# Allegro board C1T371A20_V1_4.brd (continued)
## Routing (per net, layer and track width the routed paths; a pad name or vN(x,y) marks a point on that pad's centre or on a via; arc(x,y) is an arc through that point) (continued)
TL_MSPIIO3: length 12.1
  TOP w0.2: U2.3 39.6,42.48 37.9,40.78 36.6,40.78 35,39.18 35,36.28 34.6,35.88 33.72,35.88 33.4,36.2 U5.7
TL_MSPIMISO: length 11.6
  TOP w0.2: U5.2 36.58,36.2 35.9,36.88 35.9,38.98 36.9,39.98 38.2,39.98 40.3,42.08 U2.5
TL_MSPIMOSI: length 11.6
  TOP w0.2: U2.1 38.9,42.78 37.7,41.58 36.39,41.58 34.1,39.29 34.1,38.38 33.83,38.11 31.97,38.11 31.77,38.3 31.77,38.59 31.93,38.75 32.86,38.75 U5.5
TL_PA0: length 22.5
  TOP w0.2: U2.30 48.65,45.99 53.26,41.38 55.5,41.38 57.9,38.98 65.5,38.98 66.6,40.08 J7.19
TL_PA1: length 15.5
  TOP w0.2: J7.20 57.6,40.08 55.8,41.88 53.26,41.88 48.8,46.34 U2.31
TL_PA2: length 14.6
  TOP w0.2: U2.32 48.95,46.69 53.06,42.58 60.76,42.58 J7.18
TL_PA3: length 34.4
  TOP w0.15: R27.2 73.02,35.08 72.82,35.08 D14.2 72.22,35.08 71.6,35.08 70.4,36.28 70.4,42.38 68.7,44.08 53.12,44.08 49.84,47.36 47.95,47.36 U2.34
TL_PA4: length 34.4
  TOP w0.15: U2.33 47.95,47.06 49.72,47.06 53,43.78 68.58,43.78 70.1,42.26 70.1,36.16 71.48,34.78 72.22,34.78 D15.2 72.82,34.78 73.02,34.78 R28.2
TL_PA5: length 14.7
  TOP w0.15: U2.35 47.95,47.76 50.55,47.76 53.03,45.28 57.02,45.28 57.92,46.18 59.2,46.18 60.22,45.16 J7.16
TL_PA6: length 14.8
  TOP w0.15: U2.36 47.95,48.06 50.67,48.06 53.16,45.58 56.9,45.58 57.8,46.48 59.1,46.48 60.32,47.7 J7.14
TL_PA7: length 63.5
  TOP w0.2: v1(46.9,48.44) U2.37 ; R1.2 25.6,53.28 v1(25.6,49.78)
  POWER w0.2: v1(46.9,48.44) 46.04,47.58 27.8,47.58 v1(25.6,49.78)
  BOTTOM w0.2: v1(46.9,48.44) 53.2,42.14 53.2,23.88 50.62,21.3 J12.7
TL_PB0: length 72.4
  TOP w0.2: 33.4,53.58 33.4,54.68 34.8,56.08 34.8,62.79 J2.3 J2.1 ; 33.4,53.58 24.3,44.48 18.5,44.48 15.7,41.68 15.7,24.58 14.8,23.68 8.5,23.68 7.12,22.3 J8.14 ; 33.4,53.58 36.25,53.58 37.1,54.43 39.15,54.43 39.6,53.98 U2.70
TL_PB1: length 50.5
  TOP w0.2: U2.71 39.25,53.83 39,54.08 37.3,54.08 36.4,53.18 33.5,53.18 24.38,44.06 18.68,44.06 16.12,41.5 16.12,23.9 14.52,22.3 J8.13
TL_PB2: length 57.3
  TOP w0.2: U2.72 38.9,53.48 38.7,53.68 37.6,53.68 36.65,52.73 33.55,52.73 24.45,43.63 18.85,43.63 16.55,41.33 16.55,23.83 15,22.28 15,21.58 14.4,20.98 8.3,20.98 7.08,19.76 J8.16
TL_PB3: length 49.6
  TOP w0.2: J8.15 14.38,19.76 15.4,20.78 15.4,22.11 16.95,23.66 16.95,41.16 19.02,43.23 24.55,43.23 33.63,52.31 U2.73
TL_PB4: length 21.5
  TOP w0.2: v1(58.6,57.08) 58,57.68 58,59.08 59.32,60.4 J7.4 ; U2.52 45.9,52.54 46.13,52.31 v1(46.53,52.31)
  POWER w0.2: v1(46.53,52.31) 47.06,51.78 52,51.78 56.7,56.48 58,56.48 v1(58.6,57.08)
TL_PB5: length 25.7
  TOP w0.2: J7.3 66.52,60.4 65.2,59.08 59.5,59.08 v1(58.6,58.18) ; U2.53 45.55,53.91 v1(45.72,54.08)
  POWER w0.2: v1(58.6,58.18) 58,58.78 56.9,58.78 51.8,53.68 46.13,53.68 v1(45.72,54.08)
TL_PB6: length 23.8
  TOP w0.2: J7.2 59.16,62.94 56.9,60.68 56.9,57.58 v1(57.4,57.08) ; U2.54 v1(45.2,52.31)
  POWER w0.2: v1(45.2,52.31) 45.77,52.88 52.4,52.88 56.6,57.08 v1(57.4,57.08)
TL_PB7: length 28.3
  TOP w0.2: U2.55 44.85,53.91 v1(45.03,54.08) ; v1(57.4,58.18) 57.4,59.48 59.5,61.58 65.2,61.58 66.56,62.94 J7.1
  POWER w0.2: v1(57.4,58.18) 57.1,58.18 52.2,53.28 45.4,53.28 45.03,53.66 v1(45.03,54.08)
TL_PC0: length 49.3
  TOP w0.2: v1(28,51.28) 28,50.98 23.2,46.18 15.7,46.18 7.06,37.54 ; v1(42.93,54.08) 43.1,53.91 U2.60 ; 7.06,37.54 7.24,37.54 7.9,36.88 7.9,35.78 7.12,35 J8.4 ; 7.06,37.54 J8.2
  POWER w0.2: v1(42.93,54.08) 42.3,54.08 41.8,54.58 41.1,54.58 40.2,55.48 33.6,55.48 29.4,51.28 v1(28,51.28)
TL_PC1: length 54
  TOP w0.2: v1(28,50.18) 23.6,45.78 16.9,45.78 9.3,38.18 9.3,34.68 7.08,32.46 ; U2.61 v1(42.75,52.28) ; 7.08,32.46 J8.6 ; 7.08,32.46 7.24,32.46 7.9,31.8 7.9,30.7 7.12,29.92 J8.8
  POWER w0.2: v1(28,50.18) 28.9,50.18 33.8,55.08 40.1,55.08 41.1,54.08 41.6,54.08 42.75,52.93 v1(42.75,52.28)
TL_PC4: length 25.7
  TOP w0.2: U2.64 v1(41.7,52.28) ; J7.12 60.26,50.24 v1(59.3,49.28)
  POWER w0.2: v1(41.7,52.28) 41.7,51.08 42.4,50.38 52.1,50.38 54.9,53.18 57.1,53.18 59.3,50.98 v1(59.3,49.28)
TL_PC5: length 14.8
  TOP w0.2: J7.10 60.3,52.78 58.7,51.18 58.7,50.18 58.01,49.49 U2.40
TL_PC6: length 16.9
  TOP w0.2: U2.41 57.66,49.84 58.3,50.48 58.3,51.58 59.05,52.33 59.05,54.23 60.14,55.32 J7.8
TL_PC7: length 18.9
  TOP w0.2: U2.42 57.41,50.19 57.9,50.68 57.9,51.98 58.6,52.68 58.6,56.18 60.28,57.86 J7.6
TL_PD0: length 57.1
  TOP w0.2: J8.18 7.04,17.22 8.4,18.58 14.2,18.58 15.8,20.18 15.8,21.98 17.4,23.58 17.4,41.08 19.2,42.88 24.8,42.88 33.88,51.96 U2.74
TL_PD1: length 51.2
  TOP w0.2: U2.75 34.03,51.61 24.89,42.48 19.37,42.48 17.8,40.91 17.8,23.41 16.2,21.81 16.2,18.98 14.44,17.22 J8.17
TL_PD2: length 58.8
  TOP w0.2: J8.20 7.1,14.68 8.4,15.98 14.4,15.98 16.6,18.18 16.6,21.65 18.2,23.25 18.2,40.75 19.53,42.08 25,42.08 34.18,51.26 U2.76
TL_PD3: length 52.8
  TOP w0.2: J8.19 14.5,14.68 17,17.18 17,21.48 18.6,23.08 18.6,40.58 19.7,41.68 25.09,41.68 34.33,50.91 U2.77
TL_PD4: length 71.7
  TOP w0.2: U2.19 45.2,37.34 v1(45.62,36.91)
  BOTTOM w0.2: J12.3 49.28,31.46 50.8,32.98 50.8,34.78 50.3,35.28 47.26,35.28 v1(45.62,36.91) 22.37,36.91 18.8,40.48 18.8,54.78 16.43,57.15 16.43,62.54 J3.8
TL_PD5: length 65
  TOP w0.2: U2.18 44.85,36.59 v1(45.62,35.81)
  BOTTOM w0.2: J12.2 47.44,34 v1(45.62,35.81) 44.96,36.48 22.2,36.48 18.3,40.38 18.3,54.58 15.9,56.98 15.9,60.53 J3.6
TL_PD6: length 74.7
  TOP w0.2: U2.17 44.5,35.14 v1(45.62,34.01) ; R13.2 15.9,55.45 J3.2
  BOTTOM w0.2: J12.5 48.7,26.38 45.1,29.98 45.1,33.49 v1(45.62,34.01) 43.96,35.68 20.69,35.68 15.57,40.8 15.57,53.81 13.93,55.45 J3.2
TL_PD7: length 77.8
  TOP w0.2: v1(45.62,32.73) 44.15,34.21 U2.16 ; R11.2 18.03,57.45 15.52,59.96 J3.4
  BOTTOM w0.2: J3.4 15.4,58.49 15.4,56.38 16,55.78 16,40.98 20.9,36.08 44.5,36.08 46.3,34.28 46.3,33.41 v1(45.62,32.73) 45.62,32.05 48.76,28.92 J12.4
TL_PE0: length 25.6
  TOP w0.2: U2.21 45.9,42.18 47,41.08 47,35.18 52.4,29.78 53.6,29.78 56,27.38 J7.30
TL_PE1: length 31.4
  TOP w0.2: J7.29 66.6,27.38 65.4,28.58 55.6,28.58 54,30.18 52.6,30.18 47.4,35.38 47.4,41.18 46.25,42.33 U2.22
TL_PE2: length 23.5
  TOP w0.2: J7.28 55.26,29.92 54.5,30.68 52.7,30.68 47.83,35.55 47.83,41.3 46.6,42.53 U2.23
TL_PE3: length 29.3
  TOP w0.2: U2.24 46.95,42.67 48.17,41.45 48.17,35.8 52.8,31.18 65.3,31.18 66.56,29.92 J7.27
TL_PE4: length 22.3
  TOP w0.2: J7.26 60.78,32.48 52.1,32.48 48.63,35.96 48.63,43.74 48.13,44.24 U2.25
TL_PE5: length 22.5
  TOP w0.2: J7.24 58.22,35 56.9,33.68 51.5,33.68 48.97,36.21 48.97,44.06 48.45,44.59 U2.26
TL_PE6: length 22.7
  TOP w0.2: U2.27 48.6,44.94 49.33,44.21 49.33,36.46 50.9,34.88 56.5,34.88 59.16,37.54 J7.22
TL_PE7: length 29.7
  TOP w0.2: U2.28 48.75,45.29 49.67,44.36 49.67,36.61 51,35.28 56.2,35.28 59.5,38.58 65.5,38.58 66.54,37.54 J7.21
TL_PF0: length 60.4
  TOP w0.2: J8.22 7.06,12.14 8.4,13.48 14.4,13.48 17.4,16.48 17.4,21.32 19,22.92 19,40.42 19.86,41.28 25.19,41.28 34.47,50.56 U2.78
TL_PF1: length 60.8
  TOP w0.2: J8.24 7.12,9.6 8.4,10.88 14.6,10.88 15.3,11.58 15.3,13.38 17.85,15.93 17.85,21.13 21.3,24.58 23.5,24.58 24.7,25.78 24.7,40.29 34.62,50.21 U2.79
TL_PF2: length 63
  TOP w0.2: U2.80 34.78,49.86 25.1,40.19 25.1,25.61 23.67,24.18 21.47,24.18 18.23,20.95 18.23,15.81 15.7,13.28 15.7,9.28 14.9,8.48 8.5,8.48 7.08,7.06 J8.26
TL_PF3: length 56.7
  TOP w0.2: U2.81 34.93,49.51 25.5,40.09 25.5,25.45 23.83,23.78 21.63,23.78 18.6,20.75 18.6,15.58 16.1,13.08 16.1,8.88 14.28,7.06 J8.25
TL_PF4: length 64.6
  TOP w0.2: J8.28 7.14,4.52 8.4,5.78 14.6,5.78 16.5,7.68 16.5,12.78 19,15.28 19,20.58 21.8,23.38 24,23.38 25.9,25.28 25.9,39.99 35.08,49.16 U2.82
TL_PF5: length 58.4
  TOP w0.2: U2.83 35.22,48.81 26.3,39.89 26.3,25.12 24.16,22.98 21.96,22.98 19.43,20.45 19.43,15.11 16.9,12.58 16.9,7.08 14.3,4.48 12.91,4.48 J8.27
TL_PF6: length 65.8
  TOP w0.2: U2.84 35.38,48.46 26.72,39.8 26.72,24.94 24.34,22.56 22.14,22.56 19.83,20.25 19.83,14.93 17.32,12.42 17.32,6.6 14,3.28 8.4,3.28 7.1,1.98 J8.30
TL_PF7: length 59.6
  TOP w0.2: U2.85 35.53,48.11 27.07,39.66 27.07,24.8 24.48,22.21 22.28,22.21 20.22,20.16 20.22,14.74 17.67,12.18 17.67,6.16 13.48,1.98 J8.29
TL_PG0: length 78.5
  TOP w0.2: U2.86 35.68,47.76 27.5,39.58 27.5,25.48 28.9,24.08 51,24.08 53.9,21.18 53.9,14.23 57,11.13 57,5.18 60.2,1.98 J7.50
TL_PG1: length 75.1
  TOP w0.2: J7.48 60.26,4.52 57.4,7.38 57.4,11.28 54.3,14.38 54.3,21.27 51.15,24.43 29.12,24.43 27.9,25.65 27.9,39.39 35.93,47.41 U2.87
TL_PG2: length 71.7
  TOP w0.2: U2.88 36.08,47.06 28.3,39.29 28.3,25.81 29.33,24.78 51.29,24.78 54.7,21.37 54.7,14.63 57.8,11.53 57.8,9.58 60.32,7.06 J7.46
TL_PG3: length 68.4
  TOP w0.2: J7.44 60.38,9.6 55.1,14.88 55.1,21.46 51.44,25.13 29.5,25.13 28.67,25.96 28.67,39.16 36.22,46.71 U2.89
TL_PG4: length 66.1
  TOP w0.2: J7.42 58.39,12.14 55.5,15.03 55.5,21.56 51.58,25.48 29.76,25.48 29.1,26.14 29.1,39.09 36.38,46.36 U2.90
TL_PG5: length 71.2
  TOP w0.2: U2.91 36.53,46.01 29.47,38.96 29.47,26.49 30.13,25.83 51.72,25.83 55.9,21.65 55.9,15.28 57.8,13.38 65.3,13.38 66.5,12.18 67.06,12.18 J7.41
TL_PG6: length 61.4
  TOP w0.2: J7.40 59.2,14.68 56.3,17.58 56.3,21.75 51.87,26.18 30.39,26.18 29.9,26.67 29.9,38.88 36.68,45.66 U2.92
TL_PG7: length 66.3
  TOP w0.2: J7.39 66.5,14.68 65.3,15.88 59,15.88 56.7,18.18 56.7,21.84 52.02,26.53 30.61,26.53 30.3,26.84 30.3,38.78 36.83,45.31 U2.93
TL_PH0: length 38.8
  TOP w0.2: J7.38 58.66,17.22 57.1,18.78 57.1,21.98 52.2,26.88 46.3,26.88 41.35,31.83 U2.8
TL_PH1: length 44.3
  TOP w0.2: J7.37 66.56,17.22 65.3,18.48 58.5,18.48 57.5,19.48 57.5,22.07 52.34,27.23 46.54,27.23 41.7,32.08 U2.9
TL_PH2: length 35.5
  TOP w0.2: J7.36 60.78,19.78 59.2,19.78 58,20.98 58,22.07 52.49,27.58 46.79,27.58 42.05,32.32 U2.10
TL_PH3: length 40.7
  TOP w0.2: J7.35 66.52,19.76 65.3,20.98 59.59,20.98 52.64,27.93 47.03,27.93 42.4,32.57 U2.11
TL_PH4: length 32.8
  TOP w0.2: U2.12 42.75,32.83 47.3,28.28 52.8,28.28 58.78,22.3 J7.34
TL_PH5: length 38.7
  TOP w0.2: U2.13 43.1,32.98 47.45,28.63 52.95,28.63 58,23.58 65.3,23.58 66.58,22.3 J7.33
TL_PH6: length 30.9
  TOP w0.2: U2.14 43.45,33.23 47.7,28.98 53.09,28.98 57.23,24.84 J7.32
TL_PH7: length 36.7
  TOP w0.2: J7.31 66.54,24.84 65.31,26.07 56.49,26.07 53.23,29.33 47.85,29.33 43.8,33.38 U2.15
TL_RST: length 11.3
  TOP w0.2: L11.2 C9.1 26.7,55.08 25.3,56.48 ; 25.3,56.48 SW1.1 ; 25.3,56.48 SW1.2
TL_SDMN0: length 44.5
  TOP w0.2: J8.21 v1(14.7,12.14)
  TOP w0.5: v1(44.3,22.28) 47.85,22.28 TP8.1 48.3,20.45 47.8,19.95 L7.1
  BOTTOM w0.2: v1(44.3,22.28) 44.3,19.98 42.6,18.28 35.6,18.28 28.36,11.04 15.8,11.04 v1(14.7,12.14)
TL_SDMN1: length 40.9
  TOP w0.2: J8.11 v1(14.7,24.84)
  TOP w0.5: L5.1 35.05,19.95 35.55,20.45 TP10.1 v1(35.55,22.63)
  BOTTOM w0.2: v1(35.55,22.63) 33.39,22.63 30.1,19.34 30.1,16.28 25.9,12.08 21.3,12.08 16.5,16.88 16.5,23.04 v1(14.7,24.84)
TL_SDMP0: length 47.8
  TOP w0.2: J8.23 v1(14.7,9.6)
  TOP w0.5: v1(45,23.08) 48.95,23.08 TP9.1 50.2,20.45 50.7,19.95 L8.1
  BOTTOM w0.2: v1(45,23.08) 45,19.98 42.87,17.85 35.77,17.85 28.57,10.65 15.75,10.65 v1(14.7,9.6)
TL_SDMP1: length 45.2
  TOP w0.2: J8.9 v1(14.7,27.38)
  TOP w0.5: v1(37.45,22.63) TP11.1 37.45,20.45 37.95,19.95 L6.1
  BOTTOM w0.2: v1(14.7,27.38) 17,25.08 17,17.08 21.5,12.58 25.7,12.58 29.6,16.48 29.6,19.48 33.3,23.18 36.91,23.18 v1(37.45,22.63)
TL_VBAT: length 46.2
  TOP w0.2: 47.3,53.68 47.15,53.68 46.95,53.48 U2.49
  TOP w0.4: C14.1 48.55,55.53 C56.1 48.55,54.43 47.9,53.78 47.4,53.78 47.3,53.68
  TOP w0.5: C14.1 49.1,55.68 49.5,56.08 R47.2 v1(50.3,57.78)
  POWER w0.5: v1(63.7,39.68) 63.7,54.48 58.5,59.68 52.2,59.68 v1(50.3,57.78)
  BOTTOM w0.5: v1(63.7,39.68) 61.56,37.54 J13.1 60.16,37.54 59.6,36.98 59.6,35.58 60.18,35 J13.3
TL_VBUS: length 56.3
  TOP w0.2: U2.50 46.6,53.78 46.8,53.98
  TOP w0.3: 46.8,53.98 47.25,54.43 C13.1 v1(47.25,56.08)
  POWER w0.5: v1(47.25,56.08) 45.2,56.08 43.8,57.48 26.1,57.48 24.3,55.68 24.3,51.38 11.1,38.18 v1(11.1,37.54)
  BOTTOM w0.5: J14.4 12.38,35 11.1,36.28 v1(11.1,37.54) J14.2
TL_VDD1P2: length 7.4
  TOP w0.5: L4.2 VDD1P2.1 ; L4.2 54.9,53.48 R39.1 R40.1 ; L4.2 C22.1 R41.1
TL_VDD3DCDC: length 25.7
  TOP w0.2: U2.44 48.63,50.89 48.76,50.76
  TOP w0.3: C24.1 48.76,50.76
  TOP w0.35: C24.1 57.1,50.76 57.4,51.05 57.4,54.18 VDD3DCDC.1 57.6,55.78 56.4,56.98 56.4,57.98 54.1,60.28 51.6,60.28 50,58.68 R44.2
TL_VDD_IR: length 3.4
  TOP w0.5: R2.1 C1.2 R4.1
TL_VDDCORE: length 7.2
  TOP w0.2: 52,48.98 51.84,49.14 U2.39
  TOP w0.35: 52,48.98 52.72,48.26 C25.1 54.58,48.26 VDDCORE.1
TL_VDDIOAMS: length 17.3
  TOP w0.2: U2.58 v1(43.8,52.28)
  TOP w0.5: VDDIOAMS.1 51.3,61.38 v1(50.25,60.33) R42.2
  POWER w0.5: v1(50.25,60.33) 49.1,59.18 49.1,55.88 48.1,54.88 44.7,54.88 43.8,53.98 v1(43.8,52.28)
  BOTTOM w0.35: C61.1 v1(43.8,52.28)
TL_VDDIOF: length 8.5
  TOP w0.2: U2.48 48.23,52.29 48.52,52.58
  TOP w0.4: 48.52,52.58 49.17,53.23 49.17,54.66 51,56.48 R46.1 51,58.38 VDD_F.1
TL_VDDIOF1: length 2.9
  TOP w0.2: C29.1 41,40.76 U2.7
TL_VDDIOPE: length 6.3
  TOP w0.2: 45.78,41.51 45.55,41.73 U2.20
  TOP w0.35: R45.2 46.5,38.28 VDDIOPE.1 45.78,39.01 C30.1 45.78,41.51
TL_VDDO3: length 167.9
  TOP w0.2: 44.6,54.48 44.5,54.38 U2.56
  TOP w0.3: 44.97,54.86 44.6,54.48
  TOP w0.35: 44.97,54.86 C53.1 C12.1 44.97,56.96 VDDO3.1 ; R45.1 46.5,34.58 v1(51.1,29.98)
  TOP w0.4: R5.2 v1(23.3,63.08)
  TOP w0.5: v1(46.6,59.08) R43.1 45.8,58.98 VDDO3.1 R47.1 R44.1 R42.1
  POWER w0.5: v1(23.3,63.08) 23.3,51.68 10.3,38.68 10.3,37.28 14.3,33.28 17.1,33.28 25.2,25.18 25.2,20.88 25.8,20.28 31.4,20.28 35.5,24.38 45.5,24.38 v1(51.1,29.98) ; v1(23.3,63.08) 25.9,63.08 28.6,60.38 45.3,60.38 v1(46.6,59.08) ; v1(23.3,63.08) 21,63.08 15,69.08 9.9,69.08 8.4,67.58 8.4,60.41 J3.1
  BOTTOM w0.35: J12.6 49.56,23.84 51.1,25.38 v1(51.1,29.98)
TL_VDECUSB: length 7.7
  TOP w0.2: 51.61,48.59 51.42,48.79 U2.38
  TOP w0.35: 51.61,48.59 52.6,47.61 C27.1 53.67,47.61 VDECUSB.1
TL_VLINE: length 30.6
  TOP w0.35: L9.2 C51.1 C17.1 C16.1 VLINE.1
  TOP w0.5: v1(35.8,54.16) VLINE.1 ; R41.2 v1(56.6,52.08)
  POWER w0.5: v1(56.6,52.08) 56.1,51.58 55.1,51.58 52.7,49.18 42.5,49.18 41,50.68 41,52.48 39.32,54.16 v1(35.8,54.16)
TL_XC1: length 12.7
  TOP w0.2: Y2.1 45.33,62.87 C7.2 42.1,57.21 42.1,55.18 41.35,54.43 U2.65
TL_XC2: length 10.4
  TOP w0.2: Y2.3 44.43,61.29 C6.2 44.43,60.11 41.72,57.41 41.72,55.3 41,54.58 U2.66
UART_5V: length 12.5
  TOP w0.2: C26.1 18.47,49.58 18.9,49.58 19.33,50.01 U1.9 ; U1.3 v1(19.83,54.18)
  TOP w0.35: C26.1 v1(16.97,48.81)
  TOP w0.4: v1(19.83,54.18) C19.1 L3.1
  POWER w0.5: v1(16.97,48.81) 17.8,49.65 17.8,52.15 v1(19.83,54.18)
UART_RX: length 1.9
  TOP w0.2: U1.5 18.07,52.61 17.67,53.01 R13.1
UART_TX: length 2.5
  TOP w0.2: U1.4 19.33,53.85 19,54.18 18.6,54.18 18.03,54.75 R11.1
USB_VBUSF: length 10.3
  TOP w0.5: J5.B4A9 77.25,49.9 77.82,49.33 77.82,45.77 77.15,45.1 J5.A4B9 75.6,45.1 74.95,44.45 D12.2 74.3,44.44 R21.2
USB_VBUSH: length 11.5
  TOP w0.5: D16.2 74.95,31.88 75.6,32.53 J6.A4B9 77.15,32.53 77.82,33.2 77.82,36.76 77.25,37.33 J6.B4A9 74.54,37.33 R25.2
USB_VBUSU: length 11.3
  TOP w0.5: R18.2 12.9,46.81 12.62,47.08 J4.B4A9 10.35,47.08 9.78,47.65 9.78,51.21 10.45,51.88 J4.A4B9 12,51.88 12.26,52.14 13.3,52.14 D7.2
N20198704: length 1.8
  TOP w0.5: L1.1 C5.2 L2.2
N20202485: length 2.8
  BOTTOM w0.2: Y1.1 26.95,55.12 C3.2 R7.1
N20202489: length 2.8
  BOTTOM w0.2: R6.1 C4.2 26.99,51.98 Y1.2
N20224092: length 7.6
  TOP w0.5: J1.1 D1.2 C2.2 L1.2
N20257999: length 2.4
  TOP w0.2: J5.A5 75.2,46.25 R20.2
N20258001: length 2.1
  TOP w0.2: R15.2 J5.B5
N20274526: length 2.8
  TOP w0.5: R2.2 72.32,67.46 D2.A
N20306435: length 2.4
  TOP w0.2: R32.2 75.2,33.68 J6.A5
N20306436: length 2.1
  TOP w0.2: R26.2 J6.B5
N20337202: length 4.3
  TOP w0.5: R35.1 C40.1 C39.2 35.25,16.4 34.75,16.9
N20337204: length 9.9
  TOP w0.5: R35.2 C47.2 35.25,7 33.47,5.21 J10.2
N20337251: length 4.3
  TOP w0.5: R36.1 37.05,14.53 C40.2 C41.1 38.05,16.5 38.45,16.9
N20337259: length 6.1
  TOP w0.5: J10.3 40.27,9.61 37.95,11.93 C48.1 R36.2
N20337346: length 4.3
  TOP w0.5: R37.1 C43.1 C42.2 48,16.4 47.5,16.9
N20337363: length 9.9
  TOP w0.5: J11.2 46.12,5.21 48,7.1 C49.2 R37.2
N20337410: length 4.3
  TOP w0.5: R38.1 49.8,14.53 C43.2 C44.1 50.8,16.5 51.2,16.9
N20337418: length 6
  TOP w0.5: J11.3 53.16,9.61 50.7,12.06 C50.1 R38.2
N20381027: length 1.2
  TOP w0.5: R22.1 D13.A
N20392329: length 1.3
  TOP w0.4: D3.A R8.2
N20392898: length 1.3
  TOP w0.4: R9.2 D4.A
N20393445: length 1.3
  TOP w0.4: D5.A R10.2
N20393873: length 1.3
  TOP w0.4: D6.A R12.2
N20430471: length 3.6
  TOP w0.2: 40.3,54.78 U2.68
  TOP w0.5: 40.3,54.78 C8.2 L2.1
N20434720: length 21.3
  TOP w0.2: v1(40.2,52.28) 40.65,52.73 U2.67 ; L11.1 v1(27.7,53.58)
  POWER w0.2: v1(27.7,53.58) 27,52.88 27,49.78 27.6,49.18 36,49.18 39.1,52.28 v1(40.2,52.28)
  BOTTOM w0.35: v1(40.2,52.28) C52.1
N20435400: length 5.5
  TOP w0.2: 49.6,51.28 49.56,51.24 U2.45
  TOP w0.4: 49.6,51.28 50.8,51.28 52.6,53.08 L4.1
N20464812: length 1.3
  TOP w0.4: C36.1 U7.1
N20464818: length 3.8
  TOP w0.4: C38.1 R34.2 U7.2 U7.3
N20464835: length 9.6
  TOP w0.3: C45.1 22.53,12.03 22.53,7.23 20.5,5.21 J9.2
N20464868: length 5.5
  TOP w0.3: J9.3 27.75,9.61 C46.1
N20464905: length 2.2
  TOP w0.4: U7.4 C37.1 R33.2
N20480616: length 2.7
  TOP w0.2: U1.12 20.83,49.96 TP7.1
N20480626: length 2.1
  TOP w0.2: U1.11 20.33,48.81 TP4.1
N20480630: length 2.4
  TOP w0.2: TP6.1 19.83,49.26 U1.10
N20480671: length 4
  TOP w0.2: U1.13 22.07,51.11 22.5,50.68 22.5,50.05 TP5.1
N20480690: length 3.2
  TOP w0.2: U1.14 22.58,51.61 TP3.1
N20480706: length 2.7
  TOP w0.2: U1.15 23.73,52.11 TP2.1
N20480721: length 2.9
  TOP w0.2: U1.16 23.23,52.61 TP1.1
N20480861: length 2.3
  TOP w0.2: J4.A5 12.81,50.73 R14.2
N20480863: length 2
  TOP w0.2: R16.2 J4.B5
N20516342: length 2.4
  TOP w0.2: U2.69 39.95,54.23 39.8,54.38
  TOP w0.3: 39.8,54.38 39.2,54.98 L9.1
N20517911: length 1.3
  TOP w0.2: 43.7,54.46 43.45,54.21 U2.59
N202577100: length 1.9
  TOP w0.2: J2.2 25.15,67.35 R3.1
N202577180: length 1.9
  TOP w0.2: R5.1 25.15,64.81 J2.4
N204754409: length 18.2
  TOP w0.2: J3.9 12.59,66.38 17.6,66.38 22.8,61.18 R1.1

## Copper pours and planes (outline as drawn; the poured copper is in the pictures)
GND on TOP: 6,0.3 5.51,0.51 5.3,1 5.3,67.43 6.1,69.38 8.05,70.18 38.8,70.18 38.8,66.28 41.8,66.28 41.8,70.18 79.55,70.18 81.5,69.38 82.3,67.43 82.3,66.23 74.8,66.23 74.8,60.63 82.3,60.63 82.3,1 82.09,0.51 81.6,0.3 ; 67 cut-outs
GND on BOTTOM: 6,0.3 5.51,0.51 5.3,1 5.3,67.43 6.1,69.38 8.05,70.18 38.8,70.18 38.8,66.28 41.8,66.28 41.8,70.18 79.55,70.18 81.5,69.38 82.3,67.43 82.3,66.23 74.8,66.23 74.8,60.63 82.3,60.63 82.3,1 82.09,0.51 81.6,0.3 ; 9 cut-outs
GND on GND: 6,0.3 5.51,0.51 5.3,1 5.3,67.43 6.1,69.38 8.05,70.18 38.8,70.18 38.8,66.28 41.8,66.28 41.8,70.18 79.55,70.18 81.5,69.38 82.3,67.43 82.3,66.23 74.8,66.23 74.8,60.63 82.3,60.63 82.3,1 82.09,0.51 81.6,0.3 ; 1 cut-out
GND on POWER: 6,0.3 5.51,0.51 5.3,1 5.3,67.43 6.1,69.38 8.05,70.18 38.8,70.18 38.8,66.28 41.8,66.28 41.8,70.18 79.55,70.18 81.5,69.38 82.3,67.43 82.3,66.23 74.8,66.23 74.8,60.63 82.3,60.63 82.3,1 82.09,0.51 81.6,0.3 ; 5 cut-outs

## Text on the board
Ref Des/Silkscreen Bottom: TLVBAT | BL3V3 | EXT3V3 | VBUS | BL_5V | TLVBUS | GND
User.Comments: RESET | IOREF | 3V3 | 5V | TX | RX | # | SCL | AREF | GND | 13 | 12 | 11 | 10 | 9 | 8 | 7 | 6 | 5 | 4 | 3 | 2 | 1 | 0 | SDA | A0 | A5 | VIN | A2 | A1 | A4 | A3 | [#=PWM] | www.arduino.cc | UNO_Rev3.01 | #4 | #3 | #1 | #2 | TOP | #5 | BOTTOM | POWER | ANALOG IN | L | ON | DIGITAL | R10 | R9 | ESD1 | D1 | X1 | E1 | E2 | C3 | C4 | C5 | Cp1 | U2 | ZU4 | C12 | C2 | U1 | R2 | R1 | R3 | R8 | U5' | U5 | C8 | C10 | D2 | F1 | C1 | T1 | R6 | U3 | R14 | R15 | ICSP | R13 | Y2 | R12 | R7 | C11 | C9 | R4 | RESET-EN | R11 | C6 | L1 | X2 | C7 | Y1 | IOL | IOH | GROUND | Xduino
Ref Des/Silkscreen Top: PC0 | PC1 | PC2 | PC3 | PB0 | PB2 | PD0 | PD2 | PF0 | PF1 | PF2 | PF4 | PF6 | LINEINN | LINEINP | AMICP | AMICN | SDMP0 | SDMN0 | SDMP1 | PF3 | SDMN1 | PF5 | PF7 | PB1 | PB3 | PD1 | PD3 | 4 Wire | 2 Wire | LINEIN | RESET | FLASH RESET | SDM1 | SDM0 | C1T371A20_V1_4 | TL3228XDK96D | 2026-01-21 | PC5 | PC4 | PA6 | PA5 | PG0 | PB6 | PB4 | PC7 | PC6 | PA2 | PA1 | PE6 | PE5 | PE4 | PE2 | PE0 | PH6 | PH4 | PH2 | PH0 | PG6 | PG4 | PG3 | PG2 | PG1 | PE7 | DMICCK | PG5 | KEY1 | KEY2 | KEY3 | KEY4 | LEDR | PB7 | PB5 | LEDB | LEDW | LEDG | DP | DM | PA0 | PE3 | PE1 | PH7 | PH5 | PH3 | PH1 | PG7 | DMICDAT | MICBIAS | EXT3V3 | USB_HS | USB | VDDO3 | GND | SWS | TDI | TDO | TCK | TMS | NC
User.9: FIGURE | SIZE | 0.3 | 0.7 | 0.9 | 1.0 | DRILL CHART: TOP to BOTTOM | ALL UNITS ARE IN MILLIMETERS | PLATED | NON-PLATED | QTY | 1289 | 4 | 10 | 2 | 6
